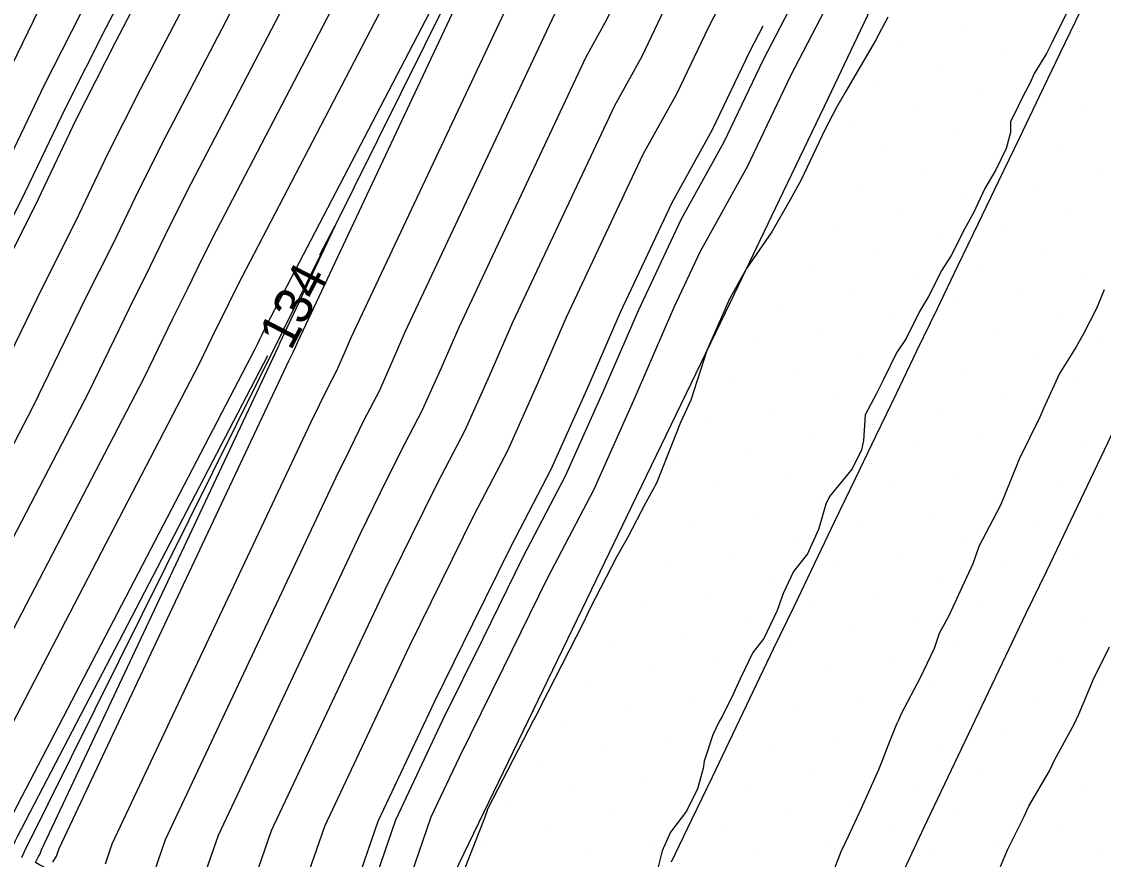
# Model space of a CAD drawing. Extents: x 2354170 to 2357230, y 866100 to 868290.
# Drawn here: x 2355241.8 to 2355299, y 866182.7 to 866227 of the extents above; entities that cross this region are included whole.
import ezdxf

# ---------------------------------------------------------------- set-up
doc = ezdxf.new("R2010")
doc.units = 0
for name, color, linetype in [('Default', 7, 'Continuous'), ('DTM Contours Major', 7, 'Continuous'), ('DTM Contours Minor', 7, 'Continuous'), ('DTM Contours Minor Text', 7, 'Continuous'), ('Exist DTM Breakline', 7, 'Continuous'), ('Exist DTM Scan Elevation Point', 7, 'Continuous'), ('Exist Roads EOP', 7, 'Continuous'), ('PH Exist DTM Breakline', 7, 'Continuous')]:
    doc.layers.add(name, color=color, linetype=linetype)

msp = doc.modelspace()

# ---------------------------------------------------------------- linework, layer by layer
at = {"layer": 'Default'}
for points in [[(2355240.662, 866218.818), (2355242.98, 866223.662), (2355245.376, 866228.393), (2355246.722, 866230.974), (2355248.773, 866235.801), (2355251.152, 866240.649), (2355253.369, 866245.609), (2355255.825, 866250.342), (2355258.182, 866255.118), (2355259.216, 866257.955), (2355261.479, 866262.883), (2355264.195, 866267.666), (2355265.927, 866268.161), (2355266.111, 866268.646), (2355275.282, 866291.07)], [(2355284.22, 866288.074), (2355279.066, 866275.895), (2355274.788, 866265.433), (2355274.085, 866263.588), (2355273.37, 866263.384), (2355272.25, 866261.41), (2355271.316, 866259.377), (2355264.23, 866239.927), (2355263.516, 866238.479), (2355262.771, 866237.044), (2355262.099, 866235.541), (2355261.379, 866234.072), (2355260.757, 866232.609), (2355252.064, 866215.937), (2355251.288, 866214.404), (2355250.537, 866212.835), (2355249.757, 866211.28), (2355248.995, 866209.715), (2355248.236, 866208.148), (2355238.535, 866189.512)], [(2355285.846, 866287.077), (2355279.628, 866272.384), (2355276.523, 866264.791), (2355275.717, 866262.673), (2355275.205, 866262.527), (2355274.404, 866261.115), (2355273.736, 866259.661), (2355265.44, 866236.888), (2355265.054, 866236.106), (2355264.652, 866235.332), (2355264.289, 866234.52), (2355263.9, 866233.726), (2355263.564, 866232.936), (2355253.401, 866213.445), (2355252.949, 866212.553), (2355252.512, 866211.638), (2355252.057, 866210.733), (2355251.614, 866209.821), (2355251.171, 866208.908), (2355239.816, 866187.091)], [(2355277.379, 866286.427), (2355269.582, 866267.361), (2355269.19, 866266.332), (2355267.865, 866265.953), (2355265.787, 866262.294), (2355264.056, 866258.524), (2355260.601, 866249.041), (2355258.901, 866245.597), (2355257.13, 866242.183), (2355255.531, 866238.606), (2355253.815, 866235.109), (2355252.336, 866231.628), (2355248.051, 866223.411), (2355246.303, 866219.959), (2355244.612, 866216.425), (2355242.855, 866212.923), (2355241.14, 866209.396)], [(2355277.941, 866282.916), (2355271.317, 866266.718), (2355270.822, 866265.417), (2355269.7, 866265.096), (2355267.941, 866261.999), (2355266.476, 866258.808), (2355261.811, 866246.003), (2355260.439, 866243.224), (2355259.01, 866240.47), (2355257.72, 866237.584), (2355256.336, 866234.763), (2355255.143, 866231.955), (2355249.389, 866220.919), (2355247.965, 866218.107), (2355246.587, 866215.228), (2355245.155, 866212.376), (2355243.758, 866209.502), (2355242.364, 866206.628), (2355235.975, 866194.353)], [(2355246.203, 866182.435), (2355246.567, 866183.488), (2355257.091, 866205.836), (2355257.531, 866206.727), (2355257.972, 866207.624), (2355258.438, 866208.514), (2355258.847, 866209.429), (2355259.237, 866210.329), (2355268.635, 866230.294), (2355269.043, 866231.029), (2355269.418, 866231.816), (2355269.821, 866232.596), (2355270.242, 866233.392), (2355270.569, 866234.185), (2355283.137, 866254.697), (2355283.85, 866256.129), (2355284.545, 866257.593), (2355285.198, 866259.066), (2355286.344, 866260.975), (2355287.134, 866262.474), (2355287.788, 866263.987), (2355295.93, 866277.918), (2355297.289, 866281.095)], [(2355248.794, 866182.033), (2355249.379, 866183.724), (2355258.397, 866202.874), (2355259.153, 866204.405), (2355259.91, 866205.944), (2355260.709, 866207.471), (2355261.412, 866209.043), (2355262.082, 866210.587), (2355270.146, 866227.718), (2355270.9, 866229.079), (2355271.596, 866230.536), (2355272.342, 866231.98), (2355273.12, 866233.454), (2355273.727, 866234.922), (2355284.459, 866252.438), (2355285.456, 866254.439), (2355286.427, 866256.485), (2355287.34, 866258.545), (2355288.319, 866260.176), (2355289.407, 866262.242), (2355290.308, 866264.325), (2355297.265, 866276.227), (2355299.022, 866280.337)], [(2355253.978, 866181.229), (2355255.004, 866184.197), (2355261.01, 866196.951), (2355262.396, 866199.759), (2355263.785, 866202.584), (2355265.252, 866205.385), (2355266.542, 866208.27), (2355267.772, 866211.104), (2355273.168, 866222.567), (2355274.615, 866225.179), (2355275.951, 866227.975), (2355277.383, 866230.748), (2355278.877, 866233.577), (2355280.042, 866236.395), (2355287.102, 866247.919), (2355288.666, 866251.06), (2355290.19, 866254.271), (2355291.624, 866257.503), (2355292.269, 866258.579), (2355293.953, 866261.776), (2355295.349, 866265.003), (2355299.933, 866272.846), (2355302.488, 866278.82)], [(2355256.57, 866180.827), (2355257.816, 866184.433), (2355262.317, 866193.989), (2355264.018, 866197.436), (2355265.723, 866200.904), (2355267.524, 866204.342), (2355269.107, 866207.884), (2355270.616, 866211.362), (2355274.678, 866219.991), (2355276.473, 866223.229), (2355278.129, 866226.695), (2355279.904, 866230.131), (2355281.755, 866233.638), (2355283.199, 866237.132), (2355288.424, 866245.66), (2355290.272, 866249.37), (2355292.072, 866253.164), (2355293.766, 866256.983), (2355294.244, 866257.78), (2355296.226, 866261.544), (2355297.869, 866265.342), (2355301.267, 866271.156), (2355304.221, 866278.062), (2355304.538, 866278.526)], [(2355243.424, 866182.533), (2355243.611, 866182.837), (2355243.754, 866183.252), (2355255.784, 866208.798), (2355255.909, 866209.05), (2355256.034, 866209.304), (2355256.166, 866209.556), (2355256.282, 866209.816), (2355256.393, 866210.071), (2355267.125, 866232.87), (2355267.185, 866232.979), (2355267.241, 866233.096), (2355267.301, 866233.212), (2355267.363, 866233.33), (2355267.412, 866233.448), (2355281.816, 866256.957), (2355282.245, 866257.819), (2355282.663, 866258.7), (2355283.057, 866259.587), (2355284.369, 866261.774), (2355284.861, 866262.707), (2355285.268, 866263.648), (2355288.913, 866269.884)], [(2355272.574, 866264.819), (2355272.453, 866264.503), (2355271.535, 866264.24), (2355270.095, 866261.705), (2355268.896, 866259.092), (2355263.021, 866242.965), (2355261.978, 866240.852), (2355260.891, 866238.757), (2355259.91, 866236.563), (2355258.857, 866234.418), (2355257.95, 866232.282), (2355250.726, 866218.428), (2355249.626, 866216.256), (2355248.562, 866214.032), (2355247.456, 866211.828), (2355246.377, 866209.609), (2355245.3, 866207.388), (2355237.255, 866191.932)], [(2355251.386, 866181.631), (2355252.191, 866183.96), (2355259.704, 866199.913), (2355260.774, 866202.082), (2355261.847, 866204.264), (2355262.981, 866206.428), (2355263.977, 866208.657), (2355264.927, 866210.845), (2355271.657, 866225.143), (2355272.758, 866227.129), (2355273.774, 866229.255), (2355274.863, 866231.364), (2355275.999, 866233.515), (2355276.884, 866235.659), (2355285.781, 866250.179), (2355287.061, 866252.749), (2355288.309, 866255.378), (2355289.482, 866258.024), (2355290.294, 866259.377), (2355291.68, 866262.009), (2355292.447, 866263.781)], [(2355270.38, 866244.092), (2355266.65, 866233.85), (2355266.592, 866233.734), (2355266.532, 866233.619), (2355266.478, 866233.498), (2355266.421, 866233.38), (2355266.371, 866233.262), (2355254.739, 866210.954), (2355254.611, 866210.701), (2355254.487, 866210.442), (2355254.358, 866210.185), (2355254.232, 866209.927), (2355254.107, 866209.668), (2355241.096, 866184.671), (2355240.896, 866184.258), (2355240.697, 866183.846), (2355240.552, 866183.537), (2355240.052, 866183.756), (2355239.506, 866184.008), (2355238.678, 866184.415), (2355237.601, 866184.948), (2355231.837, 866187.859)], [(2355252.278, 866237.461), (2355251.294, 866235.455), (2355249.529, 866231.301), (2355246.713, 866225.902), (2355244.642, 866221.81), (2355242.637, 866217.621), (2355240.554, 866213.471), (2355238.521, 866209.29), (2355236.493, 866205.108), (2355233.415, 866199.194), (2355231.374, 866194.972), (2355229.337, 866190.749), (2355229.303, 866190.676), (2355224.187, 866192.916), (2355218.604, 866195.493), (2355210.125, 866199.659), (2355199.106, 866205.115), (2355186.262, 866211.604)], [(2355284.945, 866228.899), (2355282.484, 866224.134), (2355280.188, 866219.329), (2355277.7, 866214.84), (2355276.306, 866211.878), (2355274.237, 866207.111), (2355272.067, 866202.257), (2355269.598, 866197.543), (2355267.261, 866192.791), (2355264.929, 866188.066), (2355263.441, 866184.905), (2355261.753, 866180.023)], [(2355287.632, 866227.25), (2355286.984, 866226.012), (2355285.381, 866223.299), (2355284.915, 866222.474), (2355284.316, 866221.313), (2355283.042, 866218.64), (2355282.461, 866217.587), (2355281.493, 866215.883), (2355280.144, 866213.948), (2355279.211, 866212.264), (2355279.15, 866212.136), (2355278.053, 866209.608), (2355277.208, 866206.972), (2355276.988, 866206.515), (2355276.648, 866205.796), (2355275.389, 866202.585), (2355274.806, 866201.528), (2355273.861, 866199.731), (2355273.282, 866198.706), (2355271.865, 866195.96), (2355271.717, 866195.634), (2355271.508, 866195.201), (2355269.22, 866190.721), (2355269.083, 866190.427), (2355268.866, 866190.046), (2355266.428, 866185.331), (2355266.39, 866185.2), (2355266.232, 866184.759), (2355265.04, 866181.716)], [(2355297.131, 866227.532), (2355296.328, 866225.918), (2355296.023, 866225.326), (2355295.379, 866224.263), (2355295.14, 866223.735), (2355294.821, 866223.118), (2355294.275, 866221.996), (2355294.12, 866221.717), (2355294.123, 866221.144), (2355293.901, 866220.292), (2355293.344, 866219.16), (2355292.765, 866218.174), (2355292.16, 866216.888), (2355291.711, 866216.057), (2355290.991, 866214.64), (2355290.495, 866213.857), (2355289.789, 866212.459), (2355289.311, 866211.668), (2355288.609, 866210.248), (2355288.085, 866209.474), (2355287.401, 866208.074), (2355287.009, 866207.288), (2355286.431, 866206.202), (2355286.338, 866204.846), (2355286.231, 866204.341), (2355285.742, 866203.347), (2355284.533, 866201.87), (2355284.339, 866201.466), (2355283.964, 866200.135), (2355283.373, 866198.842), (2355282.633, 866197.913), (2355282.096, 866196.744), (2355281.779, 866195.838), (2355281.073, 866194.355), (2355280.49, 866193.625), (2355279.811, 866192.235), (2355279.451, 866191.451), (2355278.86, 866190.228), (2355278.705, 866189.964), (2355278.371, 866189.257), (2355277.897, 866187.868), (2355277.845, 866187.478), (2355277.545, 866186.405), (2355276.965, 866185.232), (2355276.128, 866184.111), (2355275.687, 866183.121), (2355275.451, 866182.21)], [(2355281.008, 866226.774), (2355280.306, 866225.415), (2355278.33, 866221.279), (2355276.189, 866217.415), (2355273.461, 866211.62), (2355271.672, 866207.497), (2355269.795, 866203.3), (2355267.661, 866199.224), (2355265.639, 866195.114), (2355263.623, 866191.028), (2355260.629, 866184.669), (2355259.162, 866180.425), (2355257.245, 866177.317), (2355257.21, 866177.242), (2355261.569, 866174.915), (2355266.628, 866172.362)]]:
    msp.add_lwpolyline(points, dxfattribs=at)
at = {"layer": 'DTM Contours Major'}
for points in [[(2355272.574, 866264.819), (2355272.453, 866264.503), (2355271.535, 866264.24), (2355270.095, 866261.705), (2355268.896, 866259.092), (2355263.021, 866242.965), (2355261.978, 866240.852), (2355260.891, 866238.757), (2355259.91, 866236.563), (2355258.857, 866234.418), (2355257.95, 866232.282), (2355250.726, 866218.428), (2355249.626, 866216.256), (2355248.562, 866214.032), (2355247.456, 866211.828), (2355246.377, 866209.609), (2355245.3, 866207.388), (2355237.255, 866191.932)], [(2355251.386, 866181.631), (2355252.191, 866183.96), (2355259.704, 866199.913), (2355260.774, 866202.082), (2355261.847, 866204.264), (2355262.981, 866206.428), (2355263.977, 866208.657), (2355264.927, 866210.845), (2355271.657, 866225.143), (2355272.758, 866227.129), (2355273.774, 866229.255), (2355274.863, 866231.364), (2355275.999, 866233.515), (2355276.884, 866235.659), (2355285.781, 866250.179), (2355287.061, 866252.749), (2355288.309, 866255.378), (2355289.482, 866258.024), (2355290.294, 866259.377), (2355291.68, 866262.009), (2355292.447, 866263.781)]]:
    msp.add_lwpolyline(points, dxfattribs=at)
at = {"layer": 'DTM Contours Minor'}
for points in [[(2355177.84, 866215.898), (2355196.968, 866206.236), (2355208.539, 866200.506), (2355217.443, 866196.131), (2355223.306, 866193.425), (2355228.678, 866191.072), (2355228.706, 866191.132), (2355230.845, 866195.567), (2355232.988, 866200), (2355235.514, 866204.854), (2355237.648, 866209.255), (2355239.787, 866213.653), (2355241.979, 866218.02), (2355244.088, 866222.427), (2355246.268, 866226.732), (2355247.45, 866229)], [(2355283.264, 866229.31), (2355281.032, 866224.988), (2355278.95, 866220.629), (2355276.693, 866216.557), (2355274.409, 866211.706), (2355272.527, 866207.368), (2355270.552, 866202.952), (2355268.306, 866198.663), (2355266.18, 866194.339), (2355264.059, 866190.04), (2355261.566, 866184.748), (2355260.026, 866180.291)], [(2355242.953, 866182.268), (2355242.713, 866182.39), (2355242.505, 866182.501), (2355242.656, 866182.823), (2355242.747, 866182.971), (2355242.817, 866183.173), (2355255.349, 866209.785), (2355255.369, 866209.825), (2355255.388, 866209.864), (2355255.409, 866209.904), (2355255.427, 866209.945), (2355255.444, 866209.985), (2355258.528, 866216.536), (2355257.546, 866214.653)], [(2355299.085, 866212.818), (2355298.675, 866211.82), (2355298.015, 866210.529), (2355297.603, 866209.797), (2355296.724, 866208.385), (2355295.866, 866206.543), (2355295.679, 866206.079), (2355294.603, 866203.885), (2355294.573, 866203.813), (2355294.436, 866203.493), (2355293.616, 866201.449), (2355293.384, 866201.012), (2355292.444, 866199.227), (2355292.129, 866198.316), (2355291.465, 866196.876), (2355290.878, 866195.601), (2355290.344, 866194.62), (2355290.08, 866193.833), (2355289.342, 866192.286), (2355288.334, 866190.38), (2355288.196, 866190.046), (2355288.097, 866189.821), (2355287.632, 866188.679), (2355287.32, 866187.859), (2355287.234, 866187.685), (2355287.132, 866187.42), (2355286.212, 866185.364), (2355285.531, 866183.886), (2355285.141, 866183.075), (2355284.66, 866181.841)], [(2355254.778, 866209.33), (2355241.522, 866183.864), (2355241.425, 866183.663), (2355241.329, 866183.462), (2355241.177, 866183.14), (2355240.933, 866183.247), (2355240.668, 866183.369), (2355240.264, 866183.568), (2355239.74, 866183.827), (2355236.932, 866185.246)], [(2355293.588, 866182.295), (2355293.986, 866183.218), (2355294.852, 866184.949), (2355295.095, 866185.482), (2355296.17, 866187.332), (2355296.334, 866187.66), (2355296.454, 866187.915), (2355297.521, 866189.873), (2355297.737, 866190.359), (2355298.527, 866192.204), (2355299.37, 866193.921)]]:
    msp.add_lwpolyline(points, dxfattribs=at)
at = {"layer": 'Exist DTM Breakline'}
for points in [[(2355276.181, 866182.536), (2355277.259, 866184.791), (2355278.338, 866187.047), (2355279.416, 866189.302), (2355280.496, 866191.557), (2355281.579, 866193.81), (2355282.663, 866196.063), (2355283.746, 866198.316), (2355284.83, 866200.569), (2355285.914, 866202.822), (2355286.998, 866205.075), (2355288.082, 866207.327), (2355289.166, 866209.58), (2355290.252, 866211.832), (2355291.337, 866214.084), (2355292.422, 866216.336), (2355293.508, 866218.588), (2355294.593, 866220.841), (2355295.678, 866223.093), (2355296.763, 866225.345), (2355297.846, 866227.598)], [(2355288.506, 866182.156), (2355289.58, 866184.414), (2355290.654, 866186.671), (2355291.729, 866188.929), (2355292.803, 866191.186), (2355293.882, 866193.441), (2355294.961, 866195.696), (2355296.041, 866197.951), (2355297.12, 866200.206), (2355298.199, 866202.461), (2355299.279, 866204.716), (2355300.358, 866206.971), (2355301.438, 866209.226), (2355302.517, 866211.481), (2355303.596, 866213.736), (2355304.676, 866215.991), (2355305.755, 866218.246), (2355306.834, 866220.501), (2355307.914, 866222.756), (2355308.993, 866225.011), (2355310.077, 866227.264)]]:
    msp.add_lwpolyline(points, dxfattribs=at)
at = {"layer": 'Exist DTM Scan Elevation Point'}
for p, q in [((2355291.771, 866226.65), (2355291.771, 866226.65)), ((2355297.321, 866225.976), (2355297.321, 866225.976)), ((2355288.307, 866225.945), (2355288.307, 866225.945)), ((2355293.856, 866225.271), (2355293.856, 866225.271)), ((2355290.392, 866224.565), (2355290.392, 866224.565)), ((2355286.927, 866223.86), (2355286.927, 866223.86)), ((2355295.941, 866223.891), (2355295.941, 866223.891)), ((2355292.477, 866223.186), (2355292.477, 866223.186)), ((2355298.026, 866222.512), (2355298.026, 866222.512)), ((2355289.012, 866222.48), (2355289.012, 866222.48)), ((2355285.548, 866221.775), (2355285.548, 866221.775)), ((2355294.562, 866221.806), (2355294.562, 866221.806)), ((2355291.097, 866221.101), (2355291.097, 866221.101)), ((2355287.633, 866220.395), (2355287.633, 866220.395)), ((2355296.647, 866220.427), (2355296.647, 866220.427)), ((2355284.168, 866219.69), (2355284.168, 866219.69)), ((2355293.182, 866219.721), (2355293.182, 866219.721)), ((2355289.718, 866219.016), (2355289.718, 866219.016)), ((2355298.732, 866219.048), (2355298.732, 866219.048)), ((2355286.253, 866218.31), (2355286.253, 866218.31)), ((2355295.267, 866218.342), (2355295.267, 866218.342)), ((2355282.789, 866217.605), (2355282.789, 866217.605)), ((2355291.803, 866217.636), (2355291.803, 866217.636)), ((2355288.338, 866216.931), (2355288.338, 866216.931)), ((2355297.352, 866216.963), (2355297.352, 866216.963)), ((2355284.874, 866216.225), (2355284.874, 866216.225)), ((2355293.888, 866216.257), (2355293.888, 866216.257)), ((2355281.41, 866215.52), (2355281.41, 866215.52)), ((2355290.423, 866215.551), (2355290.423, 866215.551)), ((2355286.959, 866214.846), (2355286.959, 866214.846)), ((2355295.973, 866214.878), (2355295.973, 866214.878)), ((2355283.495, 866214.14), (2355283.495, 866214.14)), ((2355292.508, 866214.172), (2355292.508, 866214.172)), ((2355289.044, 866213.466), (2355289.044, 866213.466)), ((2355298.058, 866213.498), (2355298.058, 866213.498)), ((2355294.593, 866212.793), (2355294.593, 866212.793)), ((2355285.58, 866212.761), (2355285.58, 866212.761)), ((2355282.115, 866212.055), (2355282.115, 866212.055)), ((2355291.129, 866212.087), (2355291.129, 866212.087)), ((2355287.664, 866211.381), (2355287.664, 866211.381)), ((2355296.678, 866211.413), (2355296.678, 866211.413)), ((2355284.2, 866210.676), (2355284.2, 866210.676)), ((2355293.214, 866210.708), (2355293.214, 866210.708)), ((2355280.736, 866209.97), (2355280.736, 866209.97)), ((2355289.749, 866210.002), (2355289.749, 866210.002)), ((2355298.763, 866210.034), (2355298.763, 866210.034)), ((2355286.285, 866209.296), (2355286.285, 866209.296)), ((2355295.299, 866209.328), (2355295.299, 866209.328)), ((2355282.821, 866208.591), (2355282.821, 866208.591)), ((2355291.834, 866208.623), (2355291.834, 866208.623)), ((2355279.356, 866207.885), (2355279.356, 866207.885)), ((2355297.384, 866207.949), (2355297.384, 866207.949)), ((2355284.906, 866207.211), (2355284.906, 866207.211)), ((2355293.919, 866207.243), (2355293.919, 866207.243)), ((2355281.441, 866206.506), (2355281.441, 866206.506)), ((2355290.455, 866206.538), (2355290.455, 866206.538)), ((2355277.977, 866205.8), (2355277.977, 866205.8)), ((2355286.991, 866205.832), (2355286.991, 866205.832)), ((2355296.004, 866205.864), (2355296.004, 866205.864)), ((2355283.526, 866205.126), (2355283.526, 866205.126)), ((2355292.54, 866205.158), (2355292.54, 866205.158)), ((2355280.062, 866204.421), (2355280.062, 866204.421)), ((2355289.076, 866204.453), (2355289.076, 866204.453)), ((2355298.089, 866204.484), (2355298.089, 866204.484)), ((2355276.597, 866203.715), (2355276.597, 866203.715)), ((2355285.611, 866203.747), (2355285.611, 866203.747)), ((2355294.625, 866203.779), (2355294.625, 866203.779)), ((2355282.147, 866203.042), (2355282.147, 866203.042)), ((2355291.161, 866203.073), (2355291.161, 866203.073)), ((2355278.682, 866202.336), (2355278.682, 866202.336)), ((2355287.696, 866202.368), (2355287.696, 866202.368)), ((2355296.71, 866202.399), (2355296.71, 866202.399)), ((2355275.218, 866201.63), (2355275.218, 866201.63)), ((2355284.232, 866201.662), (2355284.232, 866201.662)), ((2355293.246, 866201.694), (2355293.246, 866201.694)), ((2355280.767, 866200.957), (2355280.767, 866200.957)), ((2355289.781, 866200.988), (2355289.781, 866200.988)), ((2355298.795, 866201.02), (2355298.795, 866201.02)), ((2355277.303, 866200.251), (2355277.303, 866200.251)), ((2355286.317, 866200.283), (2355286.317, 866200.283)), ((2355295.331, 866200.314), (2355295.331, 866200.314)), ((2355291.866, 866199.609), (2355291.866, 866199.609)), ((2355273.838, 866199.545), (2355273.838, 866199.545)), ((2355282.852, 866199.577), (2355282.852, 866199.577)), ((2355279.388, 866198.872), (2355279.388, 866198.872)), ((2355288.402, 866198.903), (2355288.402, 866198.903)), ((2355297.416, 866198.935), (2355297.416, 866198.935)), ((2355275.923, 866198.166), (2355275.923, 866198.166)), ((2355284.937, 866198.198), (2355284.937, 866198.198)), ((2355293.951, 866198.229), (2355293.951, 866198.229)), ((2355281.473, 866197.492), (2355281.473, 866197.492)), ((2355290.487, 866197.524), (2355290.487, 866197.524)), ((2355278.008, 866196.787), (2355278.008, 866196.787)), ((2355287.022, 866196.818), (2355287.022, 866196.818)), ((2355296.036, 866196.85), (2355296.036, 866196.85)), ((2355274.544, 866196.081), (2355274.544, 866196.081)), ((2355283.558, 866196.113), (2355283.558, 866196.113)), ((2355292.572, 866196.144), (2355292.572, 866196.144)), ((2355280.093, 866195.407), (2355280.093, 866195.407)), ((2355289.107, 866195.439), (2355289.107, 866195.439)), ((2355298.121, 866195.47), (2355298.121, 866195.47)), ((2355276.629, 866194.702), (2355276.629, 866194.702)), ((2355285.643, 866194.733), (2355285.643, 866194.733)), ((2355294.657, 866194.765), (2355294.657, 866194.765)), ((2355273.165, 866193.996), (2355273.165, 866193.996)), ((2355282.178, 866194.028), (2355282.178, 866194.028)), ((2355291.192, 866194.059), (2355291.192, 866194.059)), ((2355278.714, 866193.322), (2355278.714, 866193.322)), ((2355287.728, 866193.354), (2355287.728, 866193.354)), ((2355296.742, 866193.385), (2355296.742, 866193.385)), ((2355275.25, 866192.617), (2355275.25, 866192.617)), ((2355284.263, 866192.648), (2355284.263, 866192.648)), ((2355293.277, 866192.68), (2355293.277, 866192.68)), ((2355271.785, 866191.911), (2355271.785, 866191.911)), ((2355280.799, 866191.943), (2355280.799, 866191.943)), ((2355289.813, 866191.974), (2355289.813, 866191.974)), ((2355298.827, 866192.006), (2355298.827, 866192.006)), ((2355277.335, 866191.237), (2355277.335, 866191.237)), ((2355286.348, 866191.269), (2355286.348, 866191.269)), ((2355295.362, 866191.3), (2355295.362, 866191.3)), ((2355273.87, 866190.532), (2355273.87, 866190.532)), ((2355282.884, 866190.563), (2355282.884, 866190.563)), ((2355291.898, 866190.595), (2355291.898, 866190.595)), ((2355288.433, 866189.889), (2355288.433, 866189.889)), ((2355297.447, 866189.921), (2355297.447, 866189.921)), ((2355270.406, 866189.826), (2355270.406, 866189.826)), ((2355279.42, 866189.858), (2355279.42, 866189.858)), ((2355275.955, 866189.152), (2355275.955, 866189.152)), ((2355284.969, 866189.184), (2355284.969, 866189.184)), ((2355293.983, 866189.216), (2355293.983, 866189.216)), ((2355272.491, 866188.447), (2355272.491, 866188.447)), ((2355281.505, 866188.478), (2355281.505, 866188.478)), ((2355290.518, 866188.51), (2355290.518, 866188.51)), ((2355269.026, 866187.741), (2355269.026, 866187.741)), ((2355278.04, 866187.773), (2355278.04, 866187.773)), ((2355287.054, 866187.804), (2355287.054, 866187.804)), ((2355296.068, 866187.836), (2355296.068, 866187.836)), ((2355274.576, 866187.067), (2355274.576, 866187.067)), ((2355283.59, 866187.099), (2355283.59, 866187.099)), ((2355292.603, 866187.131), (2355292.603, 866187.131)), ((2355298.153, 866186.457), (2355298.153, 866186.457)), ((2355271.111, 866186.362), (2355271.111, 866186.362)), ((2355280.125, 866186.393), (2355280.125, 866186.393)), ((2355289.139, 866186.425), (2355289.139, 866186.425)), ((2355267.647, 866185.656), (2355267.647, 866185.656)), ((2355276.661, 866185.688), (2355276.661, 866185.688)), ((2355285.675, 866185.719), (2355285.675, 866185.719)), ((2355294.688, 866185.751), (2355294.688, 866185.751)), ((2355273.196, 866184.982), (2355273.196, 866184.982)), ((2355282.21, 866185.014), (2355282.21, 866185.014)), ((2355291.224, 866185.046), (2355291.224, 866185.046)), ((2355269.732, 866184.277), (2355269.732, 866184.277)), ((2355278.746, 866184.308), (2355278.746, 866184.308)), ((2355287.76, 866184.34), (2355287.76, 866184.34)), ((2355296.773, 866184.372), (2355296.773, 866184.372)), ((2355266.267, 866183.571), (2355266.267, 866183.571)), ((2355275.281, 866183.603), (2355275.281, 866183.603)), ((2355284.295, 866183.634), (2355284.295, 866183.634)), ((2355293.309, 866183.666), (2355293.309, 866183.666)), ((2355298.858, 866182.992), (2355298.858, 866182.992)), ((2355271.817, 866182.897), (2355271.817, 866182.897)), ((2355280.831, 866182.929), (2355280.831, 866182.929)), ((2355289.845, 866182.961), (2355289.845, 866182.961))]:
    msp.add_line(p, q, dxfattribs=at)
at = {"layer": 'Exist Roads EOP'}
for points in [[(2355312.899, 866282.53), (2355310.294, 866277.125), (2355307.69, 866271.719), (2355305.09, 866266.312), (2355302.495, 866260.902), (2355299.906, 866255.489), (2355297.326, 866250.072), (2355294.754, 866244.652), (2355292.186, 866239.229), (2355289.618, 866233.807), (2355287.046, 866228.386), (2355284.467, 866222.968), (2355281.878, 866217.555), (2355279.279, 866212.148), (2355276.672, 866206.744), (2355274.06, 866201.342), (2355271.446, 866195.941), (2355268.832, 866190.541), (2355266.221, 866185.139), (2355263.614, 866179.735), (2355261.649, 866175.655)], [(2355225.817, 866192.888), (2355228.423, 866198.292), (2355231.034, 866203.694), (2355233.652, 866209.093), (2355236.276, 866214.489), (2355238.904, 866219.883), (2355241.53, 866225.278), (2355244.151, 866230.675), (2355246.762, 866236.077), (2355249.363, 866241.484), (2355251.959, 866246.893), (2355254.553, 866252.303), (2355257.149, 866257.713), (2355259.749, 866263.12), (2355262.355, 866268.524), (2355264.972, 866273.924), (2355267.599, 866279.318)]]:
    msp.add_lwpolyline(points, dxfattribs=at)
at = {"layer": 'PH Exist DTM Breakline'}
msp.add_lwpolyline([(2355241.77, 866182.764), (2355241.927, 866183.098), (2355266.861, 866233.32), (2355281.117, 866263.09)], dxfattribs=at)

# ---------------------------------------------------------------- texts
at = {"layer": 'DTM Contours Minor Text'}
msp.add_text('134', height=2, rotation=62.5178, dxfattribs=at).set_placement((2355256.011, 866209.541))

doc.saveas('drawing.dxf')
